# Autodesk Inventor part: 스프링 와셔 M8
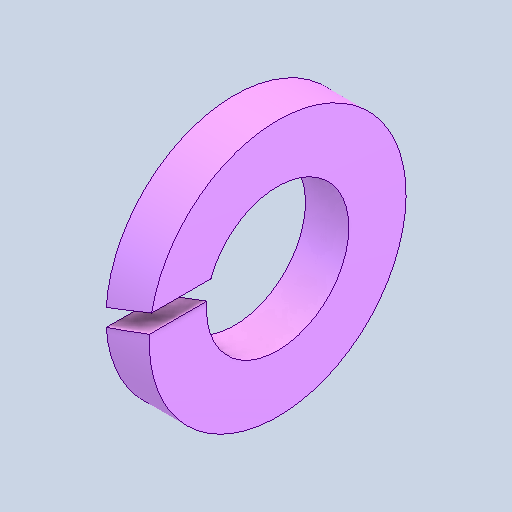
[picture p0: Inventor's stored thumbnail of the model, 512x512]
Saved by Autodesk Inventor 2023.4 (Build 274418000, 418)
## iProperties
Created: 2024-11
Part Number: 스프링 와셔 M8
Material: 강철, 연강
Description: 스프링 잠금 와셔
Document SubType Name: Modeling
Designer: EDU
Density: 7.85 g/cm^3
Appearance: 기본값
Author: jhkim
Sending System: Autodesk Inventor 2025
Preprocessor: ST-DEVELOPER v20
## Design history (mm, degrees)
feature "Solid1"
node "솔리드1"
